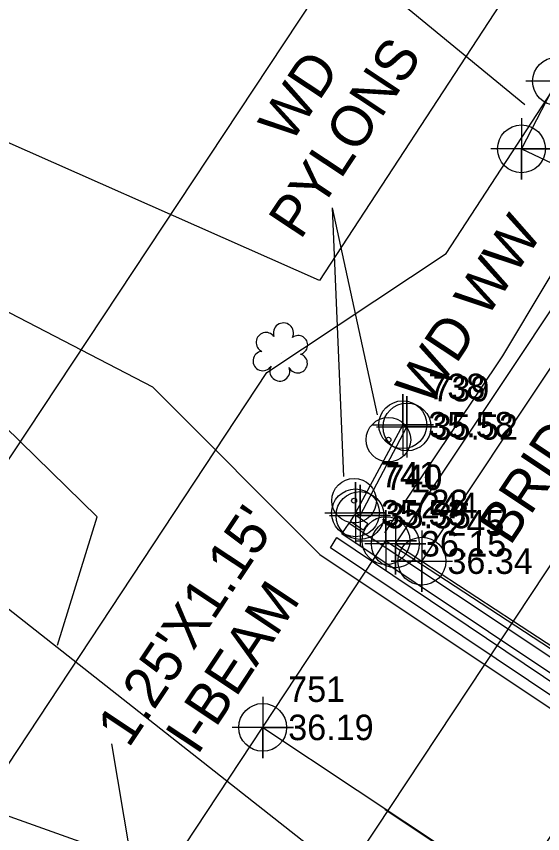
# Model space of a CAD drawing. Extents: x 2603627 to 2605187, y 896619 to 899063.
# Drawn here: x 2604513.4 to 2604564.9, y 898167.5 to 898247.7 of the extents above; entities that cross this region are included whole.
import ezdxf

# ---------------------------------------------------------------- set-up
doc = ezdxf.new("R2010")
doc.units = 0
for name, color, linetype in [('Exist Guardrail', 7, 'Continuous'), ('Exist Horizontal Alignment', 7, 'Continuous'), ('Exist Hydro Jurisdictional Stream or Body of Water', 7, 'Continuous'), ('Exist Other Culture Area Outline', 7, 'Continuous'), ('Exist Other Culture Area Outline Cogo Point CELL', 7, 'Continuous'), ('Exist Other Culture Area Outline Leader', 7, 'Continuous'), ('Exist Other Culture Located Object CELL', 7, 'Continuous'), ('Exist Other Culture Located Object Leader', 7, 'Continuous'), ('Exist Other Culture Located Object Text', 7, 'Continuous'), ('Exist Property Tie Line', 7, 'Continuous'), ('Exist Property Tie Line Leader', 7, 'Continuous'), ('Exist Right of Way Line', 7, 'Continuous'), ('Exist Roads EOP', 7, 'Continuous'), ('Exist Roads EOP Cogo Elevation', 7, 'Continuous'), ('Exist Roads EOP Cogo Number', 7, 'Continuous'), ('Exist Roads EOP Cogo Point CELL', 7, 'Continuous'), ('Exist Roads EOT', 7, 'Continuous'), ('Exist Roads EOT Cogo Elevation', 7, 'Continuous'), ('Exist Roads EOT Cogo Number', 7, 'Continuous'), ('Exist Roads EOT Cogo Point CELL', 7, 'Continuous'), ('Exist Structure Major Bridge Seam', 7, 'Continuous'), ('Exist Structure Major Bridge Seam Cogo Elevation', 7, 'Continuous'), ('Exist Structure Major Bridge Seam Cogo Number', 7, 'Continuous'), ('Exist Structure Major Bridge Seam Cogo Point CELL', 7, 'Continuous'), ('Exist Structure Major Bridge Seat Top Elevation', 7, 'Continuous'), ('Exist Structure Major Bridge Topo', 7, 'Continuous'), ('Exist Structure Major Bridge Topo Leader', 7, 'Continuous'), ('Exist Structure Major Bridge Topo Text', 7, 'Continuous'), ('Exist Structure Major Bridge WW', 7, 'Continuous'), ('Exist Structure Major Bridge WW Cogo Elevation', 7, 'Continuous'), ('Exist Structure Major Bridge WW Cogo Number', 7, 'Continuous'), ('Exist Structure Major Bridge WW Cogo Point CELL', 7, 'Continuous'), ('Exist Structure Major Bridge WW Text', 7, 'Continuous'), ('Exist Structure Major Deck Tunnel Box Culvert', 7, 'Continuous'), ('Exist Structure Major Deck Tunnel Box Culvert Cogo Number', 7, 'Continuous'), ('Exist Structure Major Deck Tunnel Box Culvert Cogo Point CELL', 7, 'Continuous'), ('Exist Utilities Telephone UG FO SUE LOS C', 7, 'Continuous'), ('Exist Vegetation Shrub CELL', 7, 'Continuous'), ('Exist Vegetation Woods Line', 7, 'Continuous')]:
    doc.layers.add(name, color=color, linetype=linetype)

# ---------------------------------------------------------------- blocks, each defined once
blk = doc.blocks.new('EXIST STRUCTURE MAJOR DECK TUNNEL BOX CULVERT COGO POINT')
at = {"layer": 'Exist Structure Major Deck Tunnel Box Culvert Cogo Point CELL'}
blk.add_lwpolyline([(-0.06, 0), (0.06, 0), (0, 0), (0, 0.06), (0, -0.06)], dxfattribs=at)
blk.add_circle((0, 0), 0.0469, dxfattribs=at)
blk = doc.blocks.new('EXIST BRIDGE SEAM COGO POINT')
at = {"layer": 'Exist Structure Major Bridge Seam Cogo Point CELL'}
blk.add_lwpolyline([(0, 0.06), (0, -0.06), (0, 0), (0.06, 0), (-0.06, 0)], dxfattribs=at)
blk.add_circle((0, 0), 0.0469, dxfattribs=at)
blk = doc.blocks.new('EXIST ROADS EOP COGO POINT')
at = {"layer": 'Exist Roads EOP Cogo Point CELL'}
blk.add_lwpolyline([(0, 0.06), (0, -0.06), (0, 0), (0.06, 0), (-0.06, 0)], dxfattribs=at)
blk.add_circle((0, 0), 0.0469, dxfattribs=at)
blk = doc.blocks.new('EXIST ROADS EOT COGO POINT')
at = {"layer": 'Exist Roads EOT Cogo Point CELL'}
blk.add_lwpolyline([(0, 0.06), (0, -0.06), (0, 0), (-0.06, 0), (0.06, 0)], dxfattribs=at)
blk.add_circle((0, 0), 0.0469, dxfattribs=at)
blk = doc.blocks.new('EXIST STRUCTURE MAJOR BRIDGE WW COGO POINT')
at = {"layer": 'Exist Structure Major Bridge WW Cogo Point CELL'}
blk.add_lwpolyline([(-0.06, 0), (0.06, 0), (0, 0), (0, 0.06), (0, -0.06)], dxfattribs=at)
blk.add_circle((0, 0), 0.0469, dxfattribs=at)
blk = doc.blocks.new('EXIST OTHER CULTURE AREA OUTLINE COGO POINT')
at = {"layer": 'Exist Other Culture Area Outline Cogo Point CELL'}
blk.add_lwpolyline([(0, 0.06), (0, -0.06), (0, 0), (0.06, 0), (-0.06, 0)], dxfattribs=at)
blk.add_circle((0, 0), 0.0469, dxfattribs=at)

msp = doc.modelspace()

# ---------------------------------------------------------------- linework, layer by layer
at = {"layer": 'Exist Guardrail'}
msp.add_lwpolyline([(2604549.447, 898197.005), (2604551.688, 898200.424), (2604561.034, 898214.376), (2604574.047, 898236.144), (2604583.438, 898252.897), (2604603.34, 898290.06), (2604614.453, 898307.438), (2604661.781, 898380.221)], dxfattribs=at)
at = {"layer": 'Exist Horizontal Alignment'}
msp.add_line((2604537.349, 898151.011), (2604647.762, 898317.915), dxfattribs=at)
at = {"layer": 'Exist Hydro Jurisdictional Stream or Body of Water'}
msp.add_line((2604545.668, 898193.174), (2604572.086, 898175.527), dxfattribs=at)
for points in [[(2604479.384, 898242.662), (2604480.506, 898241.559), (2604504.82, 898222.675), (2604526.692, 898211.338), (2604543.098, 898194.89), (2604545.668, 898193.174)], [(2604456.84, 898208.658), (2604461.28, 898204.404), (2604485.607, 898185.458), (2604503.536, 898172.482), (2604524.142, 898165.128), (2604526.341, 898163.681)]]:
    msp.add_lwpolyline(points, dxfattribs=at)
at = {"layer": 'Exist Other Culture Area Outline'}
msp.add_lwpolyline([(2604572.88, 898237.533), (2604566.28, 898241.293), (2604562.846, 898234.669), (2604569.416, 898231.58), (2604572.88, 898237.533)], dxfattribs=at)
at = {"layer": 'Exist Other Culture Area Outline Leader'}
msp.add_line((2604563.191, 898238.978), (2604530.317, 898266.037), dxfattribs=at)
at = {"layer": 'Exist Other Culture Located Object CELL'}
for centre, radius in [((2604549.811, 898206.148), 2.18), ((2604549.811, 898206.148), 0.24), ((2604546.448, 898200.17), 2.18), ((2604546.448, 898200.17), 0.24)]:
    msp.add_circle(centre, radius, dxfattribs=at)
at = {"layer": 'Exist Other Culture Located Object Leader'}
for p in [(2604548.734, 898208.603), (2604545.428, 898202.545)]:
    msp.add_line(p, (2604544.327, 898228.877), dxfattribs=at)
at = {"layer": 'Exist Property Tie Line'}
for p, q in [((2604545.339, 898163.743), (2604506.2, 898194.55)), ((2604549.449, 898169.943), (2604591.342, 898142.006))]:
    msp.add_line(p, q, dxfattribs=at)
at = {"layer": 'Exist Property Tie Line Leader'}
msp.add_lwpolyline([(2604517.401, 898185.991), (2604521.275, 898198.58), (2604456.508, 898261.982), (2604470.198, 898281.021)], dxfattribs=at)
at = {"layer": 'Exist Right of Way Line'}
msp.add_line((2604495.648, 898178.598), (2604606.061, 898345.502), dxfattribs=at)
at = {"layer": 'Exist Roads EOP'}
msp.add_line((2604550.488, 898195.948), (2604577.958, 898237.274), dxfattribs=at)
for points in [[(2604550.488, 898195.948), (2604553.09, 898194.244)], [(2604553.09, 898194.244), (2604562.061, 898188.367), (2604570.819, 898182.631), (2604573.101, 898181.136)]]:
    msp.add_lwpolyline(points, dxfattribs=at)
at = {"layer": 'Exist Roads EOT'}
msp.add_line((2604553.101, 898194.261), (2604580.649, 898235.671), dxfattribs=at)
at = {"layer": 'Exist Structure Major Bridge Seam'}
msp.add_line((2604537.493, 898177.943), (2604562.005, 898161.67), dxfattribs=at)
at = {"layer": 'Exist Structure Major Bridge Topo'}
for p, q in [((2604544.128, 898195.556), (2604544.764, 898196.555)), ((2604544.764, 898196.555), (2604576.151, 898175.402)), ((2604575.596, 898174.44), (2604544.128, 898195.556))]:
    msp.add_line(p, q, dxfattribs=at)
at = {"layer": 'Exist Structure Major Bridge Topo Leader'}
msp.add_line((2604524.609, 898165.133), (2604522.715, 898176.327), dxfattribs=at)
at = {"layer": 'Exist Structure Major Bridge WW'}
for p, q in [((2604551.216, 898207.623), (2604546.583, 898198.976)), ((2604547.025, 898198.717), (2604551.629, 898207.405)), ((2604551.216, 898207.623), (2604551.629, 898207.405)), ((2604546.583, 898198.976), (2604547.025, 898198.717)), ((2604545.239, 898196.91), (2604545.966, 898197.964)), ((2604545.966, 898197.964), (2604577.11, 898177.246)), ((2604576.346, 898176.142), (2604545.239, 898196.91))]:
    msp.add_line(p, q, dxfattribs=at)
msp.add_lwpolyline([(2604546.094, 898198.117), (2604546.521, 898198.815), (2604547.793, 898197.934), (2604547.346, 898197.273), (2604546.094, 898198.117)], dxfattribs=at)
at = {"layer": 'Exist Structure Major Deck Tunnel Box Culvert'}
msp.add_lwpolyline([(2604525.453, 898159.692), (2604549.566, 898196.253), (2604574.197, 898180.119), (2604549.896, 898143.345), (2604525.453, 898159.692)], dxfattribs=at)
at = {"layer": 'Exist Utilities Telephone UG FO SUE LOS C'}
for p, q in [((2604555.472, 898224.397), (2604671.199, 898402.262)), ((2604537.888, 898212.732), (2604555.472, 898224.397)), ((2604506.266, 898164.788), (2604537.888, 898212.732))]:
    msp.add_line(p, q, dxfattribs=at)
at = {"layer": 'Exist Vegetation Shrub CELL'}
msp.add_line((2604539.296, 898214.569), (2604539.296, 898214.569), dxfattribs=at)
for centre, radius, start, end in [((2604539.525, 898216.609), 0.99, 334.83907, 200.47174), ((2604537.814, 898215.696), 0.968, 35.89076, 245.42165), ((2604540.969, 898215.438), 0.929, 284.45672, 126.08612), ((2604537.496, 898213.865), 0.955, 95.10992, 327.95341), ((2604540.934, 898213.64), 0.937, 204.99133, 73.46012), ((2604539.168, 898212.885), 0.984, 151.27966, 21.38702)]:
    msp.add_arc(centre, radius, start, end, dxfattribs=at)
at = {"layer": 'Exist Vegetation Woods Line'}
msp.add_lwpolyline([(2604591.896, 898412.363), (2604622.511, 898404.04), (2604578.271, 898344.622), (2604545.929, 898277.972), (2604561.248, 898249.637), (2604543.064, 898221.767), (2604504.964, 898238.629), (2604486.583, 898253.52)], dxfattribs=at)

# ---------------------------------------------------------------- block references
at = {"layer": 'Exist Other Culture Area Outline Cogo Point CELL', "xscale": 50, "yscale": 50}
for p in [(2604566.28, 898241.293), (2604562.846, 898234.669)]:
    msp.add_blockref('EXIST OTHER CULTURE AREA OUTLINE COGO POINT', p, dxfattribs=at)
at = {"layer": 'Exist Roads EOP Cogo Point CELL', "xscale": 50, "yscale": 50}
msp.add_blockref('EXIST ROADS EOP COGO POINT', (2604550.488, 898195.948), dxfattribs=at)
at = {"layer": 'Exist Roads EOT Cogo Point CELL', "xscale": 50, "yscale": 50}
msp.add_blockref('EXIST ROADS EOT COGO POINT', (2604553.09, 898194.244), dxfattribs=at)
at = {"layer": 'Exist Structure Major Bridge Seam Cogo Point CELL', "xscale": 50, "yscale": 50}
msp.add_blockref('EXIST BRIDGE SEAM COGO POINT', (2604537.493, 898177.943), dxfattribs=at)
at = {"layer": 'Exist Structure Major Bridge WW Cogo Point CELL', "xscale": 50, "yscale": 50}
for p in [(2604551.216, 898207.623), (2604551.629, 898207.405), (2604546.583, 898198.976), (2604547.025, 898198.717)]:
    msp.add_blockref('EXIST STRUCTURE MAJOR BRIDGE WW COGO POINT', p, dxfattribs=at)
at = {"layer": 'Exist Structure Major Deck Tunnel Box Culvert Cogo Point CELL', "xscale": 50, "yscale": 50}
msp.add_blockref('EXIST STRUCTURE MAJOR DECK TUNNEL BOX CULVERT COGO POINT', (2604549.566, 898196.253), dxfattribs=at)

# ---------------------------------------------------------------- texts
at = {"layer": 'Exist Other Culture Located Object Text'}
for s, p in [('PYLONS', (2604541.188, 898225.667)), ('WD ', (2604540.221, 898235.072))]:
    msp.add_text(s, height=4, rotation=56.47848, dxfattribs=at).set_placement(p)
at = {"layer": 'Exist Roads EOP Cogo Elevation'}
msp.add_text('36.15', height=2.5, dxfattribs=at).set_placement((2604552.988, 898194.698))
at = {"layer": 'Exist Roads EOP Cogo Number'}
msp.add_text('244', height=2.5, dxfattribs=at).set_placement((2604552.988, 898198.448))
at = {"layer": 'Exist Roads EOT Cogo Elevation'}
msp.add_text('36.34', height=2.5, dxfattribs=at).set_placement((2604555.59, 898192.994))
at = {"layer": 'Exist Roads EOT Cogo Number'}
msp.add_text('245', height=2.5, dxfattribs=at).set_placement((2604555.59, 898196.744))
at = {"layer": 'Exist Structure Major Bridge Seam Cogo Elevation'}
msp.add_text('36.19', height=2.5, dxfattribs=at).set_placement((2604539.993, 898176.693))
at = {"layer": 'Exist Structure Major Bridge Seam Cogo Number'}
msp.add_text('751', height=2.5, dxfattribs=at).set_placement((2604539.993, 898180.443))
at = {"layer": 'Exist Structure Major Bridge Seat Top Elevation'}
msp.add_text("BRIDGE SEAT=33.05'", height=4, rotation=56.40944, dxfattribs=at).set_placement((2604561.73, 898195.662))
at = {"layer": 'Exist Structure Major Bridge Topo Text'}
for s, p in [("1.25'X1.15'", (2604524.358, 898175.839)), ('I-BEAM', (2604531.081, 898175.117))]:
    msp.add_text(s, height=4, rotation=56.40944, dxfattribs=at).set_placement(p)
at = {"layer": 'Exist Structure Major Bridge WW Cogo Elevation'}
for s, p in [('35.58', (2604553.716, 898206.373)), ('35.52', (2604554.129, 898206.155)), ('35.53', (2604549.083, 898197.726)), ('35.35', (2604549.525, 898197.467))]:
    msp.add_text(s, height=2.5, dxfattribs=at).set_placement(p)
at = {"layer": 'Exist Structure Major Bridge WW Cogo Number'}
for s, p in [('738', (2604553.716, 898210.123)), ('739', (2604554.129, 898209.905)), ('741', (2604549.083, 898201.476)), ('740', (2604549.525, 898201.217))]:
    msp.add_text(s, height=2.5, dxfattribs=at).set_placement(p)
at = {"layer": 'Exist Structure Major Bridge WW Text'}
msp.add_text('WD WW', height=4, rotation=56.47848, dxfattribs=at).set_placement((2604553.657, 898209.289))
at = {"layer": 'Exist Structure Major Deck Tunnel Box Culvert Cogo Number'}
msp.add_text('723', height=2.5, dxfattribs=at).set_placement((2604552.066, 898198.753))

doc.saveas('drawing.dxf')
